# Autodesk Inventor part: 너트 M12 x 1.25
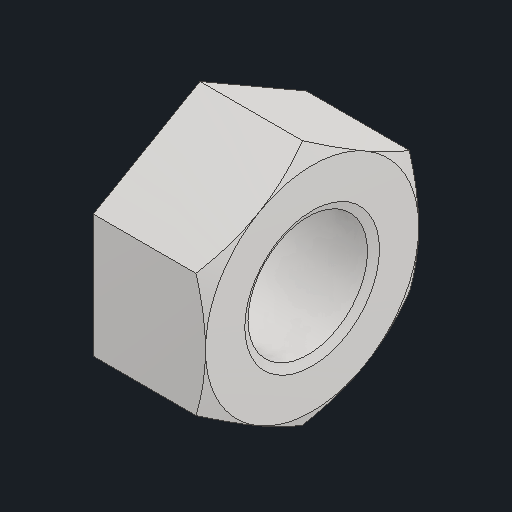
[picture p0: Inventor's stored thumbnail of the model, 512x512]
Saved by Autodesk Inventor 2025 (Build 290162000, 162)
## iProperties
Created: 2025-08
Part Number: 너트 M12 x 1.25
Material: 스테인리스강
Description: 6각 너트
Document SubType Name: Modeling
Designer: infra012
Density: 8.08 g/cm^3
Appearance: 기본값
Author: jhkim
Sending System: Autodesk Inventor 2026
Preprocessor: ST-DEVELOPER v20.1
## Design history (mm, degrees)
sketch "스케치1"
  geometry: 1 further point
  constraints: 1 other
feature "Solid1"
node "솔리드1"
